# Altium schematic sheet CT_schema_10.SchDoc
size 274 x 160 mm
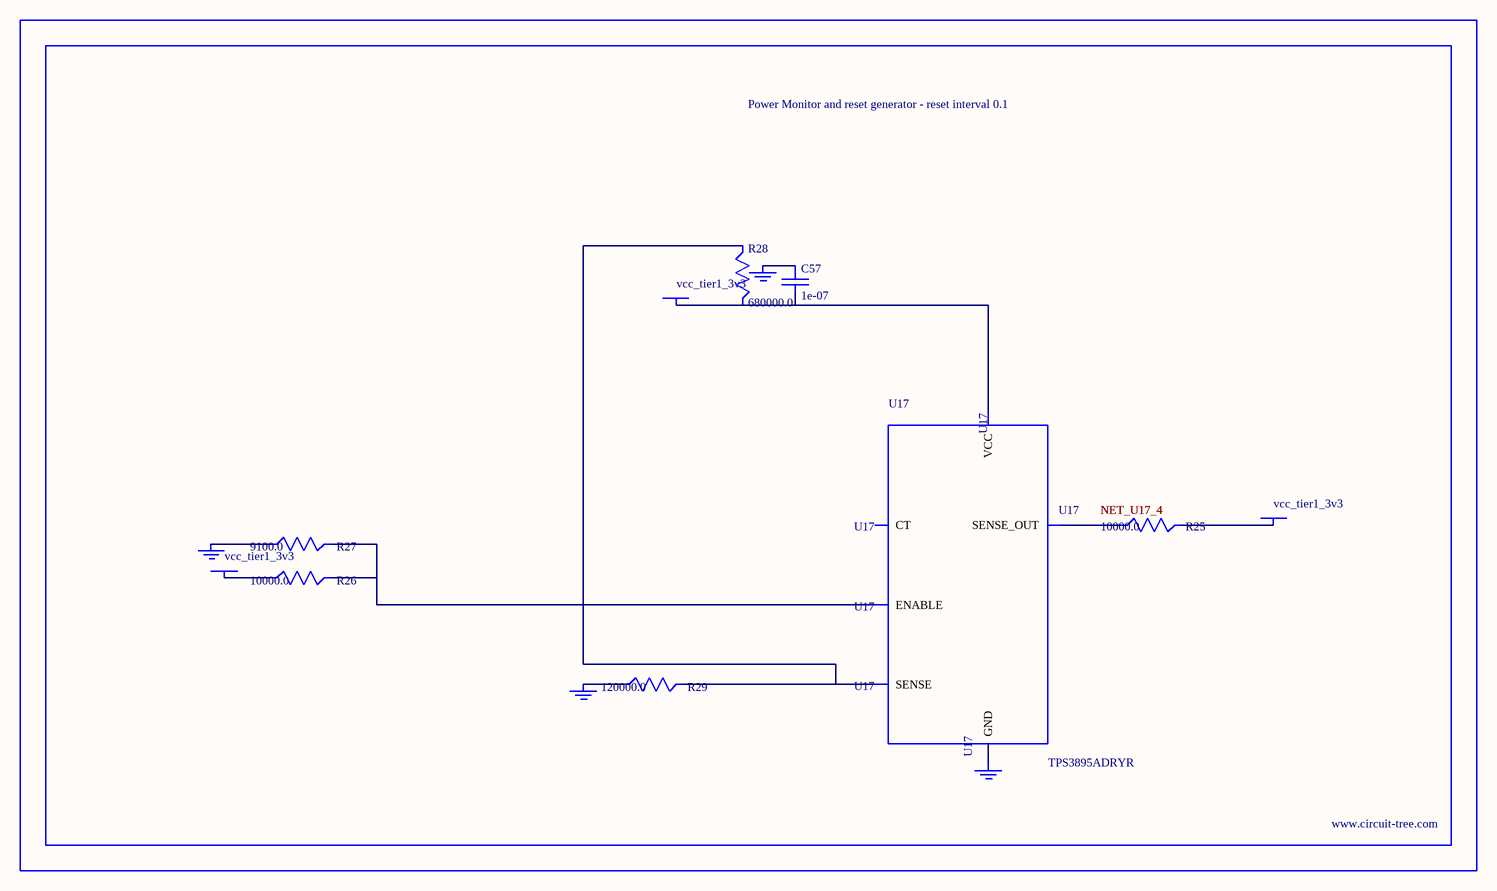
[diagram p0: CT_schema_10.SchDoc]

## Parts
BORDER9  (no value)
C57  1e-07  [C0402]
GND_INSTANCE_9_0  (no value)
GND_INSTANCE_9_1  (no value)
GND_INSTANCE_9_2  (no value)
GND_INSTANCE_9_3  (no value)
POWER_INSTANCE_9_0  vcc_tier1_3v3
POWER_INSTANCE_9_1  vcc_tier1_3v3
POWER_INSTANCE_9_2  vcc_tier1_3v3
R25  10000.0  [R0603]
R26  10000.0  [R0603]
R27  9100.0  [R0603]
R28  680000.0  [R0603]
R29  120000.0  [R0603]
U17  TPS3895ADRYR  [SON-6]

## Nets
NetC57_1: C57.1 GND_INSTANCE_9_2.0(GND)
NetC57_2: C57.2 POWER_INSTANCE_9_2.0(PWR) R28.2 U17.6(VCC)
NetGND_INSTANCE_9_0_0: GND_INSTANCE_9_0.0(GND) R27.1
NetGND_INSTANCE_9_1_0: GND_INSTANCE_9_1.0(GND) R29.1
NetGND_INSTANCE_9_3_0: GND_INSTANCE_9_3.0(GND) U17.2(GND)
NetPOWER_INSTANCE_9_0_0: POWER_INSTANCE_9_0.0(PWR) R26.1
NetPOWER_INSTANCE_9_1_0: POWER_INSTANCE_9_1.0(PWR) R25.2
NetR25_1: R25.1 U17.4(SENSE_OUT)
NetR26_2: R26.2 R27.2 U17.1(ENABLE)
NetR28_1: R28.1 R29.2 U17.3(SENSE)

Not connected (* = marked no-connect by the designer): U17 5(CT)

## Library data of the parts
BORDER9 = BORDER_PAGE9
C57 = C0402C104K3RACTU
GND_INSTANCE_9_0-GND_INSTANCE_9_3 = GND
POWER_INSTANCE_9_0-POWER_INSTANCE_9_2 = PWR
R25 R26 = RC0603JR-0710KL
R27 = RC0603JR-079K1L
R28 = RC0603JR-07680KL
R29 = RC0603JR-07120KL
